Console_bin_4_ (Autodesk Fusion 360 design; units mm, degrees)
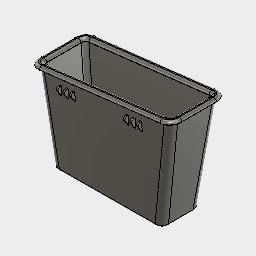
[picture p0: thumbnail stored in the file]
sketch "Sketch1"
  line L1 (-118.6747, 0) -> (0, 0)
  line L2 (-118.6747, 69.0367) -> (-118.6747, 0)
  line L3 (0, 69.0367) -> (-118.6747, 69.0367)
  line L4 (0, 0) -> (0, 69.0367)
extrude "Extrude1" new body sketch "Sketch1" blind -42.446
sketch "Sketch2" plane through (-118.6747, 0, 0) normal (-1, 0, 0) x axis (0, 0, 1)
  line L1 (0, 69.0367) -> (0, 0)
  line L2 (-42.446, 69.0367) -> (0, 69.0367)
  line L3 (-42.446, 0) -> (-42.446, 69.0367)
  line L4 (0, 0) -> (-42.446, 0)
  line L5 (-42.446, 69.0367) -> (0, 69.0367)
  line L6 (0, 69.0367) -> (0, 69.0367)
  line L7 (0, 69.0367) -> (0, 55)
extrude "Extrude2" cut sketch "Sketch2" profile of L1 L6 L7 along a picked direction blind 51.342
sketch "Sketch3"
  line L1 (-118.6747, 55) -> (0, 69.0367)
  line L2 (-118.6747, 0) -> (-118.6747, 55)
  line L3 (0, 0) -> (-118.6747, 0)
  line L4 (0, 69.0367) -> (0, 0)
  line L5 (-10, 0) -> (0, 0)
  line L6 (-10, 0) -> (0, 69.0367)
extrude "Extrude3" cut sketch "Sketch3" profile of L3 L4 L5 L6 blind -68.723
sketch "Sketch4"
  line L1 (0, 69.0367) -> (-10, 0)
  line L2 (-118.6747, 55) -> (0, 69.0367)
  line L3 (-118.6747, 0) -> (-118.6747, 55)
  line L4 (-10, 0) -> (-118.6747, 0)
  line L5 (-111.4964, 0) -> (-118.6747, 0)
  line L6 (-111.4964, 0) -> (-118.6747, 55)
extrude "Extrude4" cut sketch "Sketch4" profile of L3 L4 L5 L6 blind -63.815
draft "Draft1" Angle1 3 Angle2 3
draft "Draft2" Angle1 3 Angle2 3
fillet "Fillet1" radius 6
fillet "Fillet2" radius 6
fillet "Fillet3" radius 6
fillet "Fillet4" radius 6
fillet "Fillet5" radius 1.5
extrude "Extrude5" add of existing geometry blind 2.757
extrude "Extrude6" new body of existing geometry blind 3.586
sweep "Sweep1" TwistAngle 0 TaperAngle 0
sweep "Sweep2" TwistAngle 0 TaperAngle 0
sweep "Sweep3" TwistAngle 0 TaperAngle 0
fillet "Fillet8" radius 2.5
fillet "Fillet9" radius 0.5
sketch "Sketch5" plane through (-0.0221, 0.1865, -3.5832) normal (0.0061, -0.052, 0.9986) x axis (1, 0, -0.0062)
  line L1 (-15.7532, 1.2372) -> (-105.6153, 1.2372)
  line L2 (-6.0847, 68.2227) -> (-15.7532, 1.2372)
  line L3 (-105.6153, 1.2372) -> (-112.7174, 55.593)
  line L4 (-26.5, 58) -> (-28, 58)
  line L5 (-26.5, 50) -> (-26.5, 58)
  line L6 (-28, 50) -> (-26.5, 50)
  line L7 (-28, 58) -> (-28, 50)
  line L8 (-112.7174, 55.593) -> (-6.0847, 68.2227)
  point P6 (-28, 58)
  point P7 (-26.5, 58)
  dimension "d45" distance P6 P7 = 1.5
extrude "Extrude7" add sketch "Sketch5" profile of L4 L5 L6 L7 along normal blind 3.2
sketch "Sketch6" plane through (-26.4995, 0, 0.1631) normal (1, 0, -0.0062) x axis (-0.0062, 0, -1)
  line L1 (0.5688, 58.1081) -> (0.9846, 50.1189)
  line L2 (-2.6269, 57.9418) -> (0.5688, 58.1081)
  line L3 (-2.2111, 49.9526) -> (-2.6269, 57.9418)
  line L4 (0.9846, 50.1189) -> (-2.2111, 49.9526)
  line L5 (0.9846, 50.1189) -> (-2.4957, 55.42)
  curve K1 (-0.3901, 58.4423) -> (-2.8894, 56.2138)
extrude "Extrude8" cut sketch "Sketch6" profile of L3 L4 L5 against normal blind 6.948
sketch "Sketch7" plane through (-26.4995, 0, 0.1631) normal (1, 0, -0.0062) x axis (-0.0062, 0, -1)
  line L1 (0.9846, 50.1189) -> (-2.4957, 55.42)
  line L2 (0.5688, 58.1081) -> (0.9846, 50.1189)
  line L3 (-2.6269, 57.9418) -> (0.5688, 58.1081)
  line L4 (-2.4957, 55.42) -> (-2.6269, 57.9418)
fillet "Fillet10" radius 2
sketch "Sketch8" plane through (-26.4995, 0, 0.1631) normal (1, 0, -0.0062) x axis (-0.0062, 0, -1)
rectangular_pattern "R-Pattern1" countU 13 uSpaceDistance 71.609 vSpaceDistance 0
work_plane "WorkPlane1"
mirror "Mirror1"
offset_faces "OffsetFaces1" distance 20
shell "Shell2" innerThickness 2.5
fillet "Fillet11" radius 2.5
